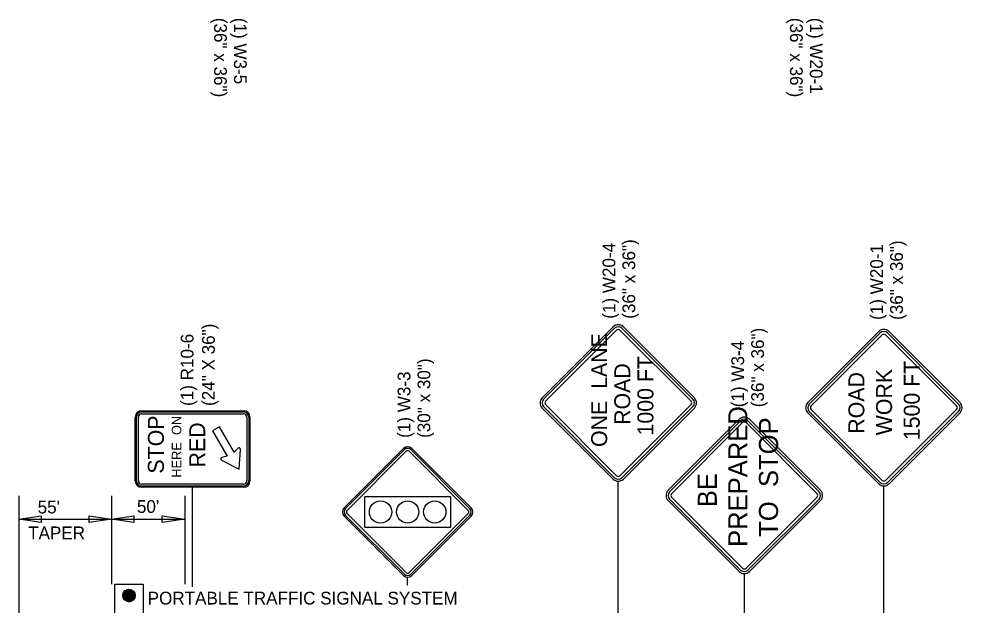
# Model space of a CAD drawing. Extents: x 1926586 to 1930787, y 596452 to 599566.
# Drawn here: x 1927876.4 to 1928320, y 596995.4 to 597271 of the extents above; entities that cross this region are included whole.
import ezdxf

# ---------------------------------------------------------------- set-up
doc = ezdxf.new("R2010")
doc.units = 0
for name, color, linetype in [('Default', 7, 'Continuous'), ('P_TC_Signs_Permanent', 7, 'Continuous'), ('P_TC_Signs_Temporary', 7, 'Continuous'), ('R_Border', 7, 'Continuous')]:
    doc.layers.add(name, color=color, linetype=linetype)

msp = doc.modelspace()

# ---------------------------------------------------------------- linework, layer by layer
at = {"layer": 'Default'}
for p, q in [((1927876.38, 597046.84), (1927876.38, 596908.29)), ((1927919.94, 597046.84), (1927919.94, 597005.26)), ((1927954.5, 597046.84), (1927954.5, 597005.26)), ((1927876.38, 597035.8), (1927886.92, 597037.39)), ((1927886.92, 597034.22), (1927876.38, 597035.8)), ((1927876.38, 597035.8), (1927919.94, 597035.8)), ((1927886.92, 597037.39), (1927886.92, 597034.22)), ((1927909.39, 597034.22), (1927909.39, 597037.39)), ((1927909.39, 597037.39), (1927919.94, 597035.8)), ((1927919.94, 597035.8), (1927909.39, 597034.22)), ((1927919.94, 597035.8), (1927930.48, 597037.39)), ((1927919.94, 597035.8), (1927954.39, 597035.8)), ((1927930.48, 597034.22), (1927919.94, 597035.8)), ((1927930.48, 597037.39), (1927930.48, 597034.22)), ((1927943.85, 597034.22), (1927943.85, 597037.39)), ((1927943.85, 597037.39), (1927954.39, 597035.8)), ((1927954.39, 597035.8), (1927943.85, 597034.22)), ((1927925.21, 596999.95), (1927928.11, 597002.85)), ((1927925.21, 596999.77), (1927928.29, 597002.84)), ((1927925.22, 597000.14), (1927927.92, 597002.84)), ((1927925.22, 596999.6), (1927928.45, 597002.83)), ((1927925.24, 597000.34), (1927927.71, 597002.82)), ((1927925.24, 596999.44), (1927928.61, 597002.81)), ((1927925.27, 596999.29), (1927928.77, 597002.78)), ((1927925.28, 597000.57), (1927927.49, 597002.77)), ((1927925.31, 596999.14), (1927928.91, 597002.75)), ((1927925.35, 596999), (1927929.05, 597002.71)), ((1927925.35, 597000.82), (1927927.24, 597002.7)), ((1927925.4, 596998.87), (1927929.19, 597002.66)), ((1927925.45, 596998.74), (1927929.31, 597002.61)), ((1927925.47, 597001.11), (1927926.94, 597002.59)), ((1927925.51, 596998.62), (1927929.44, 597002.55)), ((1927925.57, 596998.5), (1927929.56, 597002.49)), ((1927925.63, 596998.38), (1927929.67, 597002.42)), ((1927925.68, 597001.51), (1927926.55, 597002.37)), ((1927925.7, 596998.27), (1927929.78, 597002.35)), ((1927925.78, 596998.17), (1927929.89, 597002.28)), ((1927925.86, 596998.06), (1927929.99, 597002.2)), ((1927925.94, 596997.97), (1927930.09, 597002.12)), ((1927926.03, 596997.87), (1927930.18, 597002.03)), ((1927926.12, 596997.78), (1927930.27, 597001.94)), ((1927926.21, 596997.69), (1927930.36, 597001.85)), ((1927926.31, 596997.61), (1927930.44, 597001.75)), ((1927926.41, 596997.53), (1927930.52, 597001.64)), ((1927926.52, 596997.46), (1927930.6, 597001.54)), ((1927926.63, 596997.39), (1927930.67, 597001.43)), ((1927926.74, 596997.32), (1927930.73, 597001.31)), ((1927926.86, 596997.26), (1927930.79, 597001.19)), ((1927926.99, 596997.2), (1927930.85, 597001.07)), ((1927927.11, 596997.15), (1927930.9, 597000.94)), ((1927927.25, 596997.11), (1927930.95, 597000.81)), ((1927927.39, 596997.06), (1927930.99, 597000.67)), ((1927927.53, 596997.03), (1927931.03, 597000.52)), ((1927927.69, 596997), (1927931.05, 597000.37)), ((1927927.85, 596996.98), (1927931.08, 597000.21)), ((1927928.02, 596996.97), (1927931.09, 597000.04)), ((1927928.19, 596996.96), (1927931.09, 596999.86)), ((1927928.38, 596996.97), (1927931.08, 596999.67)), ((1927928.59, 596997), (1927931.06, 596999.47)), ((1927928.81, 596997.04), (1927931.02, 596999.24)), ((1927929.06, 596997.11), (1927930.95, 596998.99)), ((1927929.36, 596997.22), (1927930.83, 596998.7)), ((1927929.76, 596997.44), (1927930.61, 596998.3))]:
    msp.add_line(p, q, dxfattribs=at)
msp.add_lwpolyline([(1927921.57, 597005.26), (1927934.87, 597005.26), (1927934.87, 596980.72), (1927921.57, 596980.72)], close=True, dxfattribs=at)
msp.add_circle((1927928.15, 596999.91), 2.94, dxfattribs=at)
at = {"layer": 'P_TC_Signs_Permanent'}
for p, q in [((1927934.08, 597086.8), (1927982.08, 597086.8)), ((1927934.08, 597086.2), (1927982.08, 597086.2)), ((1927931.08, 597053.8), (1927931.08, 597083.8)), ((1927931.68, 597053.8), (1927931.68, 597083.8)), ((1927932.58, 597053.8), (1927932.58, 597083.8)), ((1927934.08, 597085.3), (1927982.08, 597085.3)), ((1927983.58, 597083.8), (1927983.58, 597053.8)), ((1927984.48, 597083.8), (1927984.48, 597053.8)), ((1927985.08, 597083.8), (1927985.08, 597053.8)), ((1928215.19, 597082.78), (1928181.78, 597049.37)), ((1928215.85, 597082.12), (1928182.44, 597048.7)), ((1928252.71, 597048.7), (1928219.3, 597082.12)), ((1928253.38, 597049.37), (1928219.96, 597082.78)), ((1928216.78, 597081.19), (1928183.37, 597047.78)), ((1928251.78, 597047.78), (1928218.37, 597081.19)), ((1928029.39, 597041.19), (1928057.24, 597069.04)), ((1928029.92, 597040.66), (1928057.77, 597068.5)), ((1928060.68, 597068.5), (1928088.53, 597040.66)), ((1928061.21, 597069.04), (1928089.06, 597041.19)), ((1928058.56, 597067.71), (1928030.72, 597039.87)), ((1928087.73, 597039.87), (1928059.89, 597067.71)), ((1927982.08, 597052.3), (1927934.08, 597052.3)), ((1927982.08, 597051.4), (1927934.08, 597051.4)), ((1927982.08, 597050.8), (1927934.08, 597050.8)), ((1928181.78, 597044.59), (1928215.19, 597011.18)), ((1928182.44, 597045.26), (1928215.85, 597011.85)), ((1928183.37, 597046.19), (1928216.78, 597012.77)), ((1928218.37, 597012.77), (1928251.78, 597046.19)), ((1928219.3, 597011.85), (1928252.71, 597045.26)), ((1928219.96, 597011.18), (1928253.38, 597044.59)), ((1928057.77, 597009.9), (1928029.92, 597037.75)), ((1928030.72, 597038.54), (1928058.56, 597010.7)), ((1928059.89, 597010.7), (1928087.73, 597038.54)), ((1928088.53, 597037.75), (1928060.68, 597009.9)), ((1928057.24, 597009.37), (1928029.39, 597037.22)), ((1928089.06, 597037.22), (1928061.21, 597009.37))]:
    msp.add_line(p, q, dxfattribs=at)
for points in [[(1927979.33, 597069.11), (1927977.68, 597067.36), (1927970.8, 597079.29), (1927967.39, 597077.32), (1927974.27, 597065.4), (1927971.9, 597064.85)], [(1927971.74, 597063.5), (1927980.06, 597059.3), (1927980.57, 597068.57)]]:
    msp.add_lwpolyline(points, dxfattribs=at)
msp.add_lwpolyline([(1928079.47, 597032.08), (1928079.47, 597046.33), (1928038.97, 597046.33), (1928038.97, 597032.08)], close=True, dxfattribs=at)
for centre in [(1928046.47, 597039.2), (1928059.22, 597039.2), (1928071.97, 597039.2)]:
    msp.add_circle(centre, 5.25, dxfattribs=at)
for centre, radius, start, end in [((1927934.08, 597083.8), 3, 90, 180), ((1927934.08, 597083.8), 2.4, 90, 180), ((1927982.08, 597083.8), 3, 360, 90), ((1927982.08, 597083.8), 2.4, 360, 90), ((1927934.08, 597083.8), 1.5, 90, 180), ((1927982.08, 597083.8), 1.5, 360, 90), ((1928217.58, 597080.39), 3.37, 45, 135), ((1928217.58, 597080.39), 2.44, 45, 135), ((1928217.58, 597080.39), 1.13, 45, 135), ((1927979.85, 597068.61), 0.72, 356.857, 136.6377), ((1928059.22, 597067.05), 2.81, 45, 135), ((1928059.22, 597067.05), 2.06, 45, 135), ((1927972.06, 597064.14), 0.72, 103.0349, 243.2286), ((1928059.22, 597067.05), 0.937, 45, 135), ((1927934.08, 597053.8), 3, 180, 270), ((1927934.08, 597053.8), 2.4, 180, 270), ((1927934.08, 597053.8), 1.5, 180, 270), ((1927982.08, 597053.8), 3, 270, 360), ((1927982.08, 597053.8), 2.4, 270, 360), ((1927982.08, 597053.8), 1.5, 270, 360), ((1928184.17, 597046.98), 3.37, 135, 225), ((1928184.17, 597046.98), 2.44, 135, 225), ((1928184.17, 597046.98), 1.13, 135, 225), ((1928250.99, 597046.98), 1.13, 315, 45), ((1928250.99, 597046.98), 2.44, 315, 45), ((1928250.99, 597046.98), 3.37, 315, 45), ((1928031.38, 597039.2), 2.81, 135, 225), ((1928031.38, 597039.2), 2.06, 135, 225), ((1928031.38, 597039.2), 0.937, 135, 225), ((1928087.07, 597039.2), 0.938, 315, 45), ((1928087.07, 597039.2), 2.06, 315, 45), ((1928087.07, 597039.2), 2.81, 315, 45), ((1928217.58, 597013.57), 3.37, 225, 315), ((1928217.58, 597013.57), 2.44, 225, 315), ((1928217.58, 597013.57), 1.13, 225, 315), ((1928059.22, 597011.36), 2.81, 225, 315), ((1928059.22, 597011.36), 2.06, 225, 315), ((1928059.22, 597011.36), 0.938, 225, 315)]:
    msp.add_arc(centre, radius, start, end, dxfattribs=at)
at = {"layer": 'P_TC_Signs_Temporary'}
for p, q in [((1928122.5, 597092.83), (1928155.91, 597126.25)), ((1928160.68, 597126.25), (1928194.1, 597092.83)), ((1928123.16, 597092.17), (1928156.57, 597125.58)), ((1928124.09, 597091.24), (1928157.5, 597124.65)), ((1928159.09, 597124.65), (1928192.5, 597091.24)), ((1928160.02, 597125.58), (1928193.43, 597092.17)), ((1928247.43, 597090.61), (1928280.84, 597124.02)), ((1928248.1, 597089.95), (1928281.51, 597123.36)), ((1928249.02, 597089.02), (1928282.44, 597122.43)), ((1928284.03, 597122.43), (1928317.44, 597089.02)), ((1928284.95, 597123.36), (1928318.37, 597089.95)), ((1928285.62, 597124.02), (1928319.03, 597090.61)), ((1928155.91, 597054.65), (1928122.5, 597088.06)), ((1928156.57, 597055.31), (1928123.16, 597088.72)), ((1928157.5, 597056.24), (1928124.09, 597089.65)), ((1928192.5, 597089.65), (1928159.09, 597056.24)), ((1928193.43, 597088.72), (1928160.02, 597055.31)), ((1928194.1, 597088.06), (1928160.68, 597054.65)), ((1928281.51, 597053.09), (1928248.1, 597086.5)), ((1928282.44, 597054.02), (1928249.02, 597087.43)), ((1928317.44, 597087.43), (1928284.03, 597054.02)), ((1928318.37, 597086.5), (1928284.95, 597053.09)), ((1928280.84, 597052.43), (1928247.43, 597085.84)), ((1928319.03, 597085.84), (1928285.62, 597052.43))]:
    msp.add_line(p, q, dxfattribs=at)
for centre, radius, start, end in [((1928158.3, 597123.86), 3.37, 45, 135), ((1928158.3, 597123.86), 2.44, 45, 135), ((1928158.3, 597123.86), 1.12, 45, 135), ((1928283.23, 597121.64), 3.37, 45, 135), ((1928283.23, 597121.64), 2.44, 45, 135), ((1928283.23, 597121.64), 1.12, 45, 135), ((1928124.89, 597090.45), 3.37, 135, 225), ((1928124.89, 597090.45), 2.44, 135, 225), ((1928124.89, 597090.45), 1.13, 135, 225), ((1928191.71, 597090.45), 1.13, 315, 45), ((1928191.71, 597090.45), 2.44, 315, 45), ((1928191.71, 597090.45), 3.37, 315, 45), ((1928249.82, 597088.23), 3.37, 135, 225), ((1928249.82, 597088.23), 2.44, 135, 225), ((1928249.82, 597088.23), 1.13, 135, 225), ((1928316.64, 597088.23), 1.13, 315, 45), ((1928316.64, 597088.23), 2.44, 315, 45), ((1928316.64, 597088.23), 3.37, 315, 45), ((1928158.3, 597057.04), 2.44, 225, 315), ((1928158.3, 597057.04), 1.12, 225, 315), ((1928158.3, 597057.04), 3.37, 225, 315), ((1928283.23, 597054.82), 3.37, 225, 315), ((1928283.23, 597054.82), 2.44, 225, 315), ((1928283.23, 597054.82), 1.12, 225, 315)]:
    msp.add_arc(centre, radius, start, end, dxfattribs=at)
at = {"layer": 'R_Border'}
for p, q in [((1927958.08, 597004.05), (1927958.08, 597050.8)), ((1928158.3, 596976.89), (1928158.3, 597053.66)), ((1928283.23, 596976.89), (1928283.23, 597051.44)), ((1928059.22, 597004.78), (1928059.22, 597008.55)), ((1928217.58, 596976.89), (1928217.58, 597010.2))]:
    msp.add_line(p, q, dxfattribs=at)

# ---------------------------------------------------------------- texts
at = {"layer": 'Default'}
for s, p in [("  55' ", (1927880.75, 597038.51)), ("50'", (1927931.9, 597038.75)), ('TAPER', (1927880.75, 597026.37)), ('PORTABLE TRAFFIC SIGNAL SYSTEM', (1927936.96, 596995.69))]:
    msp.add_text(s, height=6, rotation=360, dxfattribs=at).set_placement(p)
at = {"layer": 'P_TC_Signs_Permanent'}
for s, height, p in [('STOP', 7.5, (1927944.58, 597057.24)), ('HERE  ON', 4.5, (1927952.8, 597055.3)), ('RED', 7.5, (1927964.02, 597060.13))]:
    msp.add_text(s, height=height, rotation=90, dxfattribs=at).set_placement(p)
at = {"layer": 'P_TC_Signs_Temporary'}
for s, height, p in [('ONE  LANE', 7.5, (1928153.05, 597069.75)), ('ROAD', 7.5, (1928163.92, 597080.14)), ('1000 FT', 7.5, (1928174.8, 597075.16)), ('1500 FT', 7.5, (1928300.06, 597072.94)), (' ROAD ', 7.5, (1928274.02, 597073.2)), ('WORK', 7.5, (1928287.04, 597075.24)), ('PREPARED', 9, (1928219.05, 597022.74)), ('TO  STOP', 9, (1928233.45, 597027.52)), ('BE', 9, (1928204.65, 597041.43))]:
    msp.add_text(s, height=height, rotation=90, dxfattribs=at).set_placement(p)
at = {"layer": 'R_Border'}
for s, height, rotation, p in [('(36" x 36")', 5.9996, 270, (1927968.19, 597271.52)), ('(1) W3-5', 6, 270, (1927977.55, 597271.52)), ('(36" x 36")', 5.9996, 270, (1928239.05, 597271.52)), ('(1) W20-1', 6, 270, (1928248.41, 597271.52)), ('(36" x 36")', 5.9996, 90, (1928166.25, 597130.03)), ('(36" x 36")', 5.9996, 90, (1928292.15, 597129.49)), ('(1) W20-4', 6, 90, (1928156.89, 597130.03)), ('(1) W20-1', 6, 90, (1928282.79, 597129.49)), ('(24" X 36")', 5.9996, 90, (1927968.51, 597089.04)), ('(1) R10-6', 6, 90, (1927958.51, 597089.04)), ('(36" x 36")', 5.9996, 90, (1928226.81, 597088.43)), ('(1) W3-4', 6, 90, (1928217.45, 597088.43)), ('(30" x 30")', 5.9996, 90, (1928069.89, 597074.03)), ('(1) W3-3', 6, 90, (1928060.52, 597074.03))]:
    msp.add_text(s, height=height, rotation=rotation, dxfattribs=at).set_placement(p)

doc.saveas('drawing.dxf')
